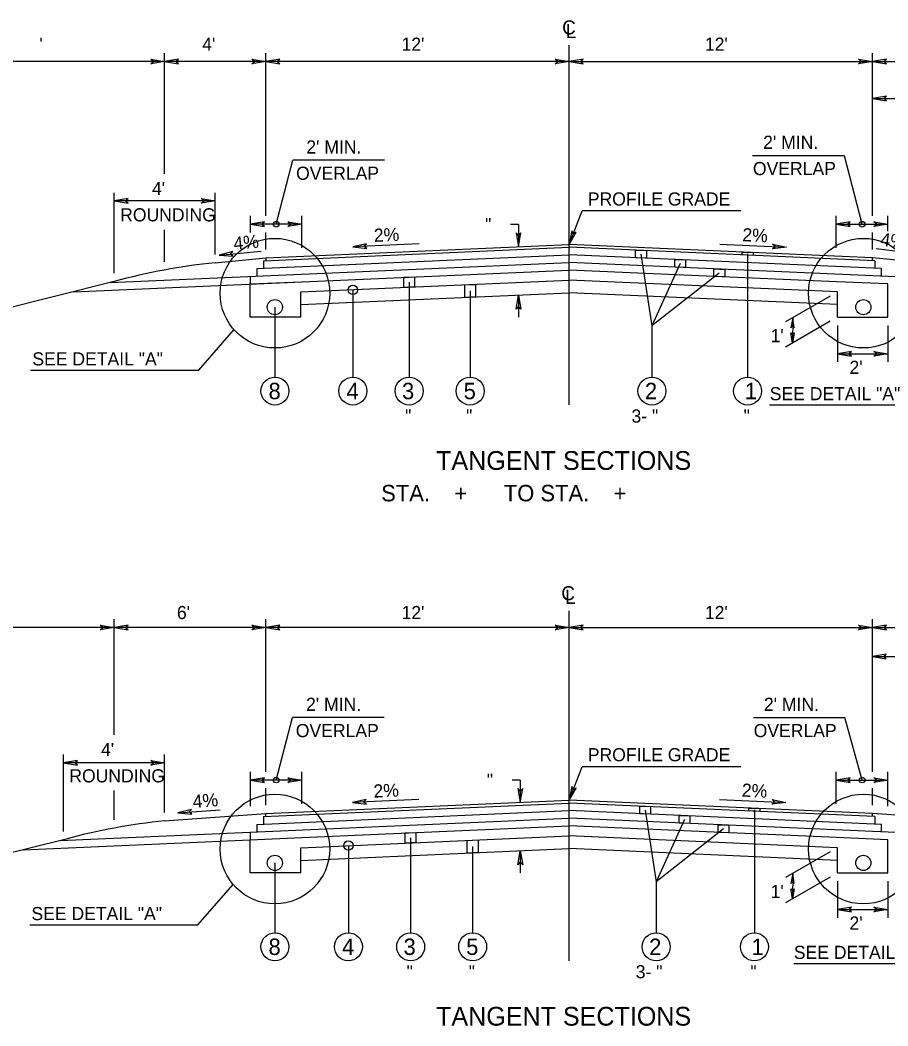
# Model space of a CAD drawing. Extents: x -540 to 1231, y -564 to 421.
# Drawn here: x 225.2 to 317.7, y 179.1 to 286.3 of the extents above; entities that cross this region are included whole.
import ezdxf

# ---------------------------------------------------------------- set-up
doc = ezdxf.new("R2010")
doc.units = 0
doc.layers.add('1', color=7, linetype='Continuous')
doc.layers.add('Des_ Drain_ Ftrs', color=7, linetype='Continuous')

msp = doc.modelspace()

# ---------------------------------------------------------------- linework, layer by layer
at = {"layer": '1'}
for p, q in [((283.71, 245.31), (283.71, 283.66)), ((240.6, 281.9), (215.18, 281.9)), ((240.6, 269.95), (240.6, 282.78)), ((251.38, 281.9), (240.6, 281.9)), ((251.38, 265.45), (251.38, 282.78)), ((283.71, 281.9), (251.38, 281.9)), ((283.71, 281.9), (316.04, 281.9)), ((316.04, 265.45), (316.04, 282.78)), ((316.04, 281.9), (326.82, 281.9)), ((316.04, 277.98), (333.01, 277.98)), ((252.48, 264.57), (254.27, 271.4)), ((264.04, 271.4), (254.27, 271.4)), ((303.27, 271.9), (313.03, 271.9)), ((314.94, 264.57), (313.05, 271.85)), ((235.21, 259.34), (235.21, 267.93)), ((245.99, 267.05), (235.22, 267.05)), ((245.99, 261.35), (245.99, 267.93)), ((283.71, 262.4), (285.09, 265.98)), ((302, 265.98), (285.09, 265.98)), ((249.74, 263.69), (249.74, 265.45)), ((255.22, 262.04), (255.22, 265.45)), ((312.19, 262.04), (312.19, 265.45)), ((317.68, 263.83), (317.68, 265.45)), ((240.6, 260.57), (240.6, 263.98)), ((255.22, 264.57), (249.74, 264.57)), ((251.38, 261.87), (251.38, 263.69)), ((278.33, 264.54), (277.45, 264.54)), ((278.33, 264.54), (278.33, 262.17)), ((312.19, 264.57), (317.68, 264.57)), ((316.04, 261.87), (316.04, 263.69)), ((246.4, 261.27), (250.88, 261.71)), ((251.14, 260.68), (283.71, 262.11)), ((251.37, 260.99), (283.71, 262.4)), ((267.73, 262.48), (260.65, 262.17)), ((316.04, 260.99), (283.71, 262.4)), ((316.28, 260.68), (283.71, 262.11)), ((299.79, 262.44), (306.88, 262.13)), ((320.91, 261.39), (316.45, 261.93)), ((234.79, 258.35), (283.71, 260.49)), ((245.99, 260.47), (251.37, 260.99)), ((250.44, 259.84), (283.71, 261.3)), ((251.14, 260.68), (251.14, 259.88)), ((251.38, 260.99), (251.38, 260.69)), ((316.98, 259.84), (283.71, 261.3)), ((332.63, 258.35), (283.71, 260.49)), ((291.37, 261.37), (292.54, 253.74)), ((302.73, 261.41), (302.73, 248.28)), ((316.03, 260.69), (316.03, 261)), ((321.43, 260.47), (316.04, 260.99)), ((316.28, 260.68), (316.28, 259.88)), ((230.87, 257.37), (283.71, 259.68)), ((250.44, 259.84), (250.44, 259.04)), ((312.2, 258.44), (283.71, 259.68)), ((295.55, 260.38), (292.54, 253.74)), ((299.72, 259.37), (292.54, 253.74)), ((316.98, 259.84), (316.98, 259.04)), ((235.22, 258.46), (215.18, 253.45)), ((249.73, 259), (249.73, 258.2)), ((249.73, 258.2), (255.22, 258.44)), ((255.12, 257.35), (283.71, 258.6)), ((266.66, 258.39), (266.66, 248.28)), ((312.3, 257.35), (283.71, 258.6)), ((317.69, 258.2), (312.2, 258.44)), ((249.73, 254.66), (249.73, 258.2)), ((255.12, 254.66), (255.12, 257.35)), ((255.12, 256), (283.71, 257.25)), ((260.66, 257.57), (260.66, 248.28)), ((273.16, 257.47), (273.16, 248.28)), ((312.3, 256), (283.71, 257.25)), ((312.3, 254.66), (312.3, 257.35)), ((312.3, 257.35), (312.3, 257.35)), ((317.69, 254.66), (317.69, 258.2)), ((278.33, 257.02), (278.33, 254.65)), ((311.54, 256.91), (306.78, 254.17)), ((252.35, 255.73), (252.35, 248.28)), ((255.12, 254.66), (249.73, 254.66)), ((311.54, 254.22), (306.76, 251.46)), ((307.54, 254.61), (307.52, 251.9)), ((312.3, 254.66), (317.69, 254.66)), ((244.24, 249.01), (247.98, 253.33)), ((292.54, 253.74), (292.54, 248.28)), ((312.3, 253.78), (312.3, 249.89)), ((317.69, 253.78), (317.69, 249.89)), ((312.3, 250.77), (317.69, 250.77)), ((226.31, 249.01), (244.24, 249.01)), ((305.08, 245.31), (323.86, 245.31)), ((283.71, 186.09), (283.71, 223.37)), ((235.22, 210.17), (235.22, 222.49)), ((251.38, 206.22), (251.38, 222.49)), ((316.04, 206.22), (316.04, 222.49)), ((235.22, 221.61), (209.84, 221.61)), ((251.38, 221.61), (235.22, 221.61)), ((283.71, 221.61), (251.38, 221.61)), ((283.71, 221.61), (316.04, 221.61)), ((316.04, 221.61), (332.2, 221.61)), ((316.03, 218.51), (338.39, 218.51)), ((252.48, 205.34), (254.24, 212.01)), ((264.01, 212.01), (254.24, 212.01)), ((303.35, 212.01), (313.11, 212.01)), ((314.94, 205.34), (313.11, 212.01)), ((229.83, 199.87), (229.83, 208.07)), ((240.6, 201.88), (240.6, 208.07)), ((240.6, 207.19), (229.83, 207.19)), ((249.74, 202.54), (249.74, 206.22)), ((255.22, 202.82), (255.22, 206.22)), ((283.71, 203.19), (285.09, 206.76)), ((302, 206.76), (285.09, 206.76)), ((312.19, 202.82), (312.19, 206.22)), ((317.68, 202.54), (317.68, 206.22)), ((255.22, 205.34), (249.74, 205.34)), ((278.51, 205.33), (277.63, 205.33)), ((278.51, 205.33), (278.51, 202.96)), ((312.19, 205.34), (317.68, 205.34)), ((235.22, 201.1), (235.22, 204.21)), ((251.38, 202.65), (251.38, 204.46)), ((316.04, 202.65), (316.04, 204.46)), ((251.14, 201.46), (283.71, 202.89)), ((251.37, 201.77), (283.71, 203.19)), ((267.7, 203.25), (260.62, 202.94)), ((316.03, 201.77), (283.71, 203.19)), ((316.28, 201.46), (283.71, 202.89)), ((299.73, 203.26), (306.82, 202.95)), ((240.6, 201), (251.37, 201.77)), ((242.01, 201.85), (246.5, 202.18)), ((250.43, 200.62), (283.71, 202.08)), ((251.37, 201.47), (251.37, 201.77)), ((316.99, 200.62), (283.71, 202.08)), ((291.82, 202.12), (292.99, 194.5)), ((303.46, 202.16), (303.46, 189.06)), ((326.82, 201), (316.03, 201.77)), ((316.03, 201.47), (316.03, 201.77)), ((229.45, 198.9), (283.71, 201.27)), ((250.43, 200.62), (250.43, 199.81)), ((251.14, 201.46), (251.14, 200.65)), ((255.22, 199.21), (283.71, 200.46)), ((337.95, 198.9), (283.71, 201.27)), ((312.2, 199.21), (283.71, 200.46)), ((296, 201.14), (292.99, 194.5)), ((316.28, 201.46), (316.28, 200.65)), ((316.98, 200.62), (316.98, 199.82)), ((249.73, 199.78), (249.73, 198.97)), ((255.12, 198.13), (283.71, 199.38)), ((312.3, 198.13), (283.71, 199.38)), ((300.18, 200.13), (292.99, 194.5)), ((229.95, 199.02), (209.84, 194)), ((225.53, 197.92), (249.73, 198.97)), ((249.73, 198.97), (255.22, 199.21)), ((249.73, 195.44), (249.73, 198.97)), ((260.19, 198.35), (260.19, 189.06)), ((266.82, 199.18), (266.82, 189.06)), ((317.69, 198.97), (312.2, 199.21)), ((317.69, 195.44), (317.69, 198.97)), ((255.12, 195.44), (255.12, 198.13)), ((255.12, 196.78), (283.71, 198.03)), ((273.43, 198.26), (273.43, 189.06)), ((278.51, 197.81), (278.51, 195.44)), ((312.3, 196.78), (283.71, 198.03)), ((311.54, 197.69), (306.78, 194.94)), ((312.3, 195.44), (312.3, 198.13)), ((312.3, 198.13), (312.3, 198.13)), ((252.35, 196.51), (252.35, 189.06)), ((255.12, 195.44), (249.73, 195.44)), ((307.54, 195.38), (307.52, 192.68)), ((312.3, 195.44), (317.69, 195.44)), ((244.15, 189.9), (247.89, 194.22)), ((292.99, 194.5), (292.99, 189.06)), ((311.54, 195), (306.76, 192.24)), ((312.3, 194.56), (312.3, 190.67)), ((317.69, 194.56), (317.69, 190.67)), ((312.3, 191.55), (317.69, 191.55)), ((226.22, 189.9), (244.15, 189.9)), ((307.65, 185.78), (326.44, 185.78))]:
    msp.add_line(p, q, dxfattribs=at)
for points in [[(290.8, 261.8), (291.95, 261.75), (291.95, 260.94), (290.8, 260.99)], [(302.16, 261.6), (303.31, 261.55), (303.31, 261.25), (302.16, 261.3)], [(294.98, 260.81), (296.12, 260.76), (296.12, 259.95), (294.98, 260)], [(299.15, 259.81), (300.3, 259.76), (300.3, 258.95), (299.15, 259)], [(266.08, 258.91), (267.23, 258.96), (267.23, 257.88), (266.08, 257.83)], [(272.59, 258.11), (273.73, 258.16), (273.73, 256.82), (272.59, 256.77)], [(291.25, 202.56), (292.4, 202.51), (292.4, 201.7), (291.25, 201.75)], [(295.43, 201.56), (296.57, 201.51), (296.57, 200.71), (295.43, 200.76)], [(302.88, 202.35), (304.03, 202.3), (304.03, 202), (302.88, 202.05)], [(299.6, 200.57), (300.75, 200.52), (300.75, 199.71), (299.6, 199.76)], [(266.24, 199.7), (267.39, 199.75), (267.39, 198.67), (266.24, 198.62)], [(272.86, 198.91), (274, 198.96), (274, 197.61), (272.86, 197.56)]]:
    msp.add_lwpolyline(points, close=True, dxfattribs=at)
for centre, radius in [((252.48, 264.57), 0.3), ((314.94, 264.57), 0.3), ((252.35, 257.22), 5.84), ((315.07, 257.22), 5.84), ((260.66, 257.57), 0.5), ((252.35, 255.73), 0.808), ((315.07, 255.73), 0.808), ((252.35, 246.79), 1.49), ((260.66, 246.79), 1.49), ((266.66, 246.79), 1.49), ((273.16, 246.79), 1.49), ((292.54, 246.79), 1.49), ((302.73, 246.79), 1.49), ((252.48, 205.34), 0.3), ((314.94, 205.34), 0.3), ((252.35, 197.99), 5.84), ((315.07, 197.99), 5.84), ((260.19, 198.35), 0.5), ((252.35, 196.51), 0.808), ((315.07, 196.51), 0.808), ((252.35, 187.57), 1.49), ((260.19, 187.57), 1.49), ((266.82, 187.57), 1.49), ((273.43, 187.57), 1.49), ((292.99, 187.57), 1.49), ((303.46, 187.57), 1.49)]:
    msp.add_circle(centre, radius, dxfattribs=at)
for centre, end in [((252.87, 193.63), 105.2381), ((247.49, 134.16), 105.1262)]:
    msp.add_arc(centre, 67.19, 95.8795, end, dxfattribs=at)
at = {"layer": 'Des_ Drain_ Ftrs'}
for points in [[(240.6, 281.9), (239.12, 281.65), (239.41, 281.9), (239.12, 282.14)], [(240.6, 281.9), (242.09, 281.65), (241.8, 281.9), (242.09, 282.14)], [(251.38, 281.9), (249.89, 281.65), (250.19, 281.9), (249.89, 282.14)], [(251.38, 281.9), (252.87, 281.65), (252.57, 281.9), (252.87, 282.14)], [(283.71, 281.9), (282.22, 281.65), (282.52, 281.9), (282.22, 282.14)], [(283.71, 281.9), (285.2, 281.65), (284.9, 281.9), (285.2, 282.14)], [(316.04, 281.9), (314.55, 281.65), (314.85, 281.9), (314.55, 282.14)], [(316.04, 281.9), (317.53, 281.65), (317.23, 281.9), (317.53, 282.14)], [(316.04, 277.98), (317.53, 277.73), (317.23, 277.98), (317.53, 278.23)], [(235.22, 267.05), (236.7, 266.81), (236.41, 267.05), (236.7, 267.3)], [(245.99, 267.05), (244.5, 266.81), (244.8, 267.05), (244.5, 267.3)], [(249.74, 264.57), (251.23, 264.32), (250.93, 264.57), (251.23, 264.82)], [(255.22, 264.57), (253.74, 264.32), (254.03, 264.57), (253.74, 264.82)], [(312.19, 264.57), (313.68, 264.32), (313.39, 264.57), (313.68, 264.82)], [(317.68, 264.57), (316.19, 264.32), (316.49, 264.57), (316.19, 264.82)], [(278.33, 262.17), (278.58, 263.66), (278.33, 263.36), (278.08, 263.66)], [(283.71, 262.4), (284.47, 263.71), (284.14, 263.52), (284.01, 263.88)], [(246.4, 261.27), (247.9, 261.17), (247.59, 261.38), (247.86, 261.66)], [(260.65, 262.17), (262.15, 261.98), (261.84, 262.22), (262.13, 262.48)], [(306.88, 262.13), (305.38, 261.95), (305.68, 262.19), (305.4, 262.45)], [(278.33, 257.02), (278.58, 255.53), (278.33, 255.82), (278.08, 255.53)], [(307.54, 254.61), (307.35, 253.52), (307.53, 253.74), (307.71, 253.52)], [(307.52, 251.9), (307.35, 252.98), (307.53, 252.77), (307.71, 252.98)], [(312.3, 250.77), (313.79, 250.52), (313.49, 250.77), (313.79, 251.02)], [(317.69, 250.77), (316.2, 250.52), (316.49, 250.77), (316.2, 251.02)], [(235.22, 221.61), (233.73, 221.36), (234.02, 221.61), (233.73, 221.86)], [(235.22, 221.61), (236.7, 221.36), (236.41, 221.61), (236.7, 221.86)], [(251.38, 221.61), (249.89, 221.36), (250.19, 221.61), (249.89, 221.86)], [(251.38, 221.61), (252.87, 221.36), (252.57, 221.61), (252.87, 221.86)], [(283.71, 221.61), (282.22, 221.36), (282.52, 221.61), (282.22, 221.86)], [(283.71, 221.61), (285.2, 221.36), (284.9, 221.61), (285.2, 221.86)], [(316.04, 221.61), (314.55, 221.36), (314.85, 221.61), (314.55, 221.86)], [(316.04, 221.61), (317.53, 221.36), (317.23, 221.61), (317.53, 221.86)], [(316.03, 218.51), (317.52, 218.26), (317.23, 218.51), (317.52, 218.76)], [(229.83, 207.19), (231.32, 206.94), (231.02, 207.19), (231.32, 207.44)], [(240.6, 207.19), (239.12, 206.94), (239.41, 207.19), (239.12, 207.44)], [(249.74, 205.34), (251.23, 205.09), (250.93, 205.34), (251.23, 205.59)], [(255.22, 205.34), (253.74, 205.09), (254.03, 205.34), (253.74, 205.59)], [(312.19, 205.34), (313.68, 205.09), (313.39, 205.34), (313.68, 205.59)], [(317.68, 205.34), (316.19, 205.09), (316.49, 205.34), (316.19, 205.59)], [(278.51, 202.96), (278.76, 204.45), (278.51, 204.15), (278.26, 204.45)], [(283.71, 203.19), (284.47, 204.49), (284.14, 204.3), (284.01, 204.66)], [(260.62, 202.94), (262.11, 202.76), (261.81, 203), (262.09, 203.26)], [(306.82, 202.95), (305.32, 202.77), (305.62, 203), (305.34, 203.26)], [(242.01, 201.85), (243.51, 201.71), (243.2, 201.94), (243.48, 202.21)], [(278.51, 197.81), (278.76, 196.32), (278.51, 196.61), (278.26, 196.32)], [(307.54, 195.38), (307.35, 194.3), (307.53, 194.51), (307.71, 194.3)], [(307.52, 192.68), (307.35, 193.76), (307.53, 193.55), (307.71, 193.76)], [(312.3, 191.55), (313.79, 191.3), (313.49, 191.55), (313.79, 191.8)], [(317.69, 191.55), (316.2, 191.3), (316.49, 191.55), (316.2, 191.8)]]:
    msp.add_lwpolyline(points, close=True, dxfattribs=at)

# ---------------------------------------------------------------- texts
at = {"layer": '1'}
for s, height, p in [("  '", 1.4, (226.2, 283.05)), ("4'", 1.4, (244.6, 283.05)), ("12'", 1.4, (265.85, 283.05)), ("12'", 1.4, (298.18, 283.05)), ("2' MIN.", 1.4, (255.7, 272.1)), ("2' MIN.", 1.4, (304.39, 272.6)), ('OVERLAP', 1.4, (303.3, 269.8)), ('OVERLAP', 1.4, (254.61, 269.3)), ("4'", 1.4, (239.25, 267.67)), ('PROFILE GRADE', 1.4, (285.7, 266.56)), ('ROUNDING', 1.4, (235.86, 264.87)), ('SEE DETAIL "A"', 1.4, (226.5, 249.52)), ("2'", 1.4, (313.59, 248.62)), ('8', 1.75, (251.67, 245.92)), ('4', 1.75, (259.99, 245.92)), ('3', 1.75, (265.9, 245.92)), ('5', 1.75, (272.47, 245.92)), ('2', 1.75, (291.79, 245.92)), ('1', 1.75, (302.43, 245.92)), ('SEE DETAIL "A"', 1.4, (305.09, 245.81)), (' "', 1.4, (265.71, 243.43)), (' "', 1.4, (272.21, 243.43)), ('3- "', 1.4, (290.36, 243.43)), (' "', 1.4, (301.79, 243.43)), ('TANGENT SECTIONS', 2, (269.53, 238.39)), ('STA.    +      TO STA.    +     ', 1.75, (263.68, 235.04)), ("6'", 1.4, (241.91, 222.49)), ("12'", 1.4, (265.85, 222.49)), ("12'", 1.4, (298.18, 222.49)), ("2' MIN.", 1.4, (255.67, 212.71)), ("2' MIN.", 1.4, (304.47, 212.71)), ('OVERLAP', 1.4, (254.58, 209.91)), ('OVERLAP', 1.4, (303.38, 209.91)), ("4'", 1.4, (233.82, 207.89)), ('PROFILE GRADE', 1.4, (285.7, 207.34)), ('ROUNDING', 1.4, (230.44, 205.09)), ('SEE DETAIL "A"', 1.4, (226.4, 190.41)), ("2'", 1.4, (313.59, 189.4)), ('8', 1.75, (251.67, 186.7)), ('4', 1.75, (259.51, 186.7)), ('3', 1.75, (266.06, 186.7)), ('5', 1.75, (272.74, 186.7)), ('2', 1.75, (292.24, 186.7)), ('1', 1.75, (303.16, 186.7)), ('SEE DETAIL "A"', 1.4, (307.66, 186.28)), (' "', 1.4, (265.87, 184.21)), (' "', 1.4, (272.49, 184.21)), ('3- "', 1.4, (290.81, 184.21)), (' "', 1.4, (302.51, 184.21)), ('TANGENT SECTIONS', 2, (269.53, 179.17))]:
    msp.add_text(s, height=height, dxfattribs=at).set_placement(p)
for s, rotation, p in [('  "', 0.1438, (273.72, 263.83)), ('2%', 2.6235, (262.93, 262.68)), ('2%', 357.3765, (302.15, 262.76)), ('4%', 5.8556, (248.01, 261.81)), ('4%', 352.7159, (316.83, 262.29)), ("1'", 0.1438, (305.19, 251.99)), ('  "', 0.1438, (273.9, 204.62)), ('2%', 2.6263, (262.89, 203.46)), ('2%', 357.3763, (302.09, 203.58)), ('4%', 4.3931, (243.64, 202.35)), ("1'", 0.1438, (305.19, 192.77))]:
    msp.add_text(s, height=1.4, rotation=rotation, dxfattribs=at).set_placement(p)
at = {"layer": 'Des_ Drain_ Ftrs'}
for s, p in [('C', (282.97, 284.79)), ('L', (283.36, 284.4)), ('C', (282.88, 224.5)), ('L', (283.28, 224.11))]:
    msp.add_text(s, height=1.5, dxfattribs=at).set_placement(p)

doc.saveas('drawing.dxf')
